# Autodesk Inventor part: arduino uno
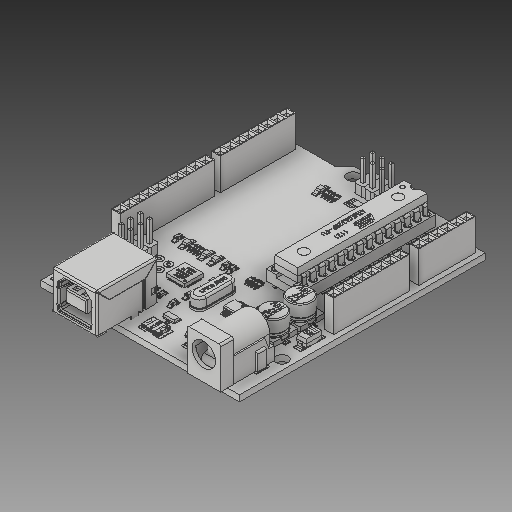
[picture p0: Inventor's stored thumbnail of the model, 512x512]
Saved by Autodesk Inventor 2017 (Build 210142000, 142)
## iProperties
Created: 2014-01
Part Number: arduino uno
Material: Générique
Description: STEP AP203
Document SubType Name: Modeling
Designer: ficho
Density: 1 g/cm^3
Appearance: Par défaut
Title: arduino uno.STEP
Author: A
Sending System: SolidWorks 2012
Preprocessor: SwSTEP 2.0
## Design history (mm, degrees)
feature "unoboard blue_1:1"
feature "47uf CAP Dcase_2:1"
feature "47uf CAP Dcase_2:2"
feature "USB SHELL_82:1"
feature "USB core_83:1"
feature "usb top contact_84:1"
feature "usb btm contact_85:1"
feature "usb btm contact_86:1"
feature "usb top contact_87:1"
feature "power jack_4:1"
feature "power jack_4:2"
feature "47uf CAP Dcase_5:1"
feature "47uf CAP Dcase_5:2"
feature "crystal_6:1"
feature "2pin_header__02_7:1"
feature "nano - reg_8:1"
feature "led_9:1"
feature "led_9:2"
feature "2pin_header__02_10:1"
feature "dip28_53:1"
feature "dip socket pin_54:1"
feature "dip socket pin_55:1"
feature "dip socket pin_56:1"
feature "dip socket pin_57:1"
feature "dip socket pin_58:1"
feature "dip socket pin_59:1"
feature "dip socket pin_60:1"
feature "dip socket pin_61:1"
feature "dip socket pin_62:1"
feature "dip socket pin_63:1"
feature "dip socket pin_64:1"
feature "dip socket pin_65:1"
feature "dip socket pin_66:1"
feature "dip socket pin_67:1"
feature "dip socket pin_68:1"
feature "dip socket pin_69:1"
feature "dip socket pin_70:1"
feature "dip socket pin_71:1"
feature "dip socket pin_72:1"
feature "dip socket pin_73:1"
feature "dip socket pin_74:1"
feature "dip socket pin_75:1"
feature "dip socket pin_76:1"
feature "dip socket pin_77:1"
feature "dip socket pin_78:1"
feature "dip socket pin_79:1"
feature "dip socket pin_80:1"
feature "dip socket pin_81:1"
feature "2pin_header__02_12:1"
feature "2pin_header__02_13:1"
feature "2pin_header__02_14:1"
feature "2pin_header__02_15:1"
feature "atmega16u2_16:1"
feature "led_17:1"
feature "led_17:2"
feature "led_18:1"
feature "led_18:2"
feature "led_19:1"
feature "led_19:2"
feature "8 PORT HEADER_20:1"
feature "8 PORT HEADER_21:1"
feature "6 PORT HEADER_22:1"
feature "10 PORT HEADER_23:1"
feature "ATMEL328P_24:1"
feature "ATMEL328P_24:2"
feature "ATMEL328P_24:3"
feature "ATMEL328P_24:4"
feature "ATMEL328P_24:5"
feature "ATMEL328P_24:6"
feature "ATMEL328P_24:7"
feature "ATMEL328P_24:8"
feature "ATMEL328P_24:9"
feature "ATMEL328P_24:10"
feature "ATMEL328P_24:11"
feature "102 RESISTOR PACK_25:1"
feature "102 RESISTOR PACK_25:2"
feature "102 RESISTOR PACK_25:3"
feature "102 RESISTOR PACK_25:4"
feature "102 RESISTOR PACK_25:5"
feature "102 RESISTOR PACK_25:6"
feature "102 RESISTOR PACK_25:7"
feature "102 RESISTOR PACK_25:8"
feature "102 RESISTOR PACK_25:9"
feature "102 RESISTOR PACK_25:10"
feature "102 RESISTOR PACK_26:1"
feature "102 RESISTOR PACK_26:2"
feature "102 RESISTOR PACK_26:3"
feature "102 RESISTOR PACK_26:4"
feature "102 RESISTOR PACK_26:5"
feature "102 RESISTOR PACK_26:6"
feature "102 RESISTOR PACK_26:7"
feature "102 RESISTOR PACK_26:8"
feature "102 RESISTOR PACK_26:9"
feature "102 RESISTOR PACK_26:10"
feature "103 RESISTOR PACK_27:1"
feature "103 RESISTOR PACK_27:2"
feature "103 RESISTOR PACK_27:3"
feature "103 RESISTOR PACK_27:4"
feature "103 RESISTOR PACK_27:5"
feature "103 RESISTOR PACK_27:6"
feature "103 RESISTOR PACK_27:7"
feature "103 RESISTOR PACK_27:8"
feature "103 RESISTOR PACK_27:9"
feature "103 RESISTOR PACK_27:10"
feature "220 RESISTOR PACK_28:1"
feature "220 RESISTOR PACK_28:2"
feature "220 RESISTOR PACK_28:3"
feature "220 RESISTOR PACK_28:4"
feature "220 RESISTOR PACK_28:5"
feature "220 RESISTOR PACK_28:6"
feature "220 RESISTOR PACK_28:7"
feature "220 RESISTOR PACK_28:8"
feature "220 RESISTOR PACK_28:9"
feature "220 RESISTOR PACK_28:10"
feature "16mhz crystal - measured_29:1"
feature "PADS001_30:1"
feature "PADS001_30:2"
feature "PADS001_30:3"
feature "PADS001_30:4"
feature "603 cap on pad_31:1"
feature "ssot3_32:1"
feature "mf-msmf050-2_33:1"
feature "603 cap on pad_34:1"
feature "603 cap on pad_35:1"
feature "lmv358_36:1"
feature "603 cap on pad_37:1"
feature "603 cap on pad_38:1"
feature "603 cap on pad_39:1"
feature "603 cap on pad_40:1"
feature "603 cap on pad_41:1"
feature "lp2985dgkr_42:1"
feature "cd1206 diode_43:1"
feature "cd1206 diode_43:2"
feature "cd1206 diode_43:3"
feature "cd1206 diode_43:4"
feature "cd1206 diode_43:5"
feature "cd1206 diode_44:1"
feature "cd1206 diode_44:2"
feature "cd1206 diode_44:3"
feature "cd1206 diode_44:4"
feature "cd1206 diode_44:5"
feature "603 resistor_45:1"
feature "603 resistor_45:2"
feature "603 resistor_45:3"
feature "603 resistor_45:4"
feature "blm21_46:1"
feature "m7 diode_47:1"
feature "MLC0603_48:1"
feature "MLC0603_48:2"
feature "MLC0603_48:3"
feature "MLC0603_48:4"
feature "MLC0603_49:1"
feature "MLC0603_49:2"
feature "MLC0603_49:3"
feature "MLC0603_49:4"
feature "RESET CORE_51:1"
feature "RESET CORE_51:2"
feature "RESET_52:1"
node "Solide1"
node "Solide2"
node "Solide3"
node "Solide4"
node "Solide5"
node "Solide6"
node "Solide7"
node "Solide8"
node "Solide9"
node "Solide10"
node "Solide11"
node "Solide12"
node "Solide13"
node "Solide14"
node "Solide15"
node "Solide16"
node "Solide17"
node "Solide18"
node "Solide19"
node "Solide20"
node "Solide21"
node "Solide22"
node "Solide23"
node "Solide24"
node "Solide25"
node "Solide26"
node "Solide27"
node "Solide28"
node "Solide29"
node "Solide30"
node "Solide31"
node "Solide32"
node "Solide33"
node "Solide34"
node "Solide35"
node "Solide36"
node "Solide37"
node "Solide38"
node "Solide39"
node "Solide40"
node "Solide41"
node "Solide42"
node "Solide43"
node "Solide44"
node "Solide45"
node "Solide46"
node "Solide47"
node "Solide48"
node "Solide49"
node "Solide50"
node "Solide51"
node "Solide52"
node "Solide53"
node "Solide54"
node "Solide55"
node "Solide56"
node "Solide57"
node "Solide58"
node "Solide59"
node "Solide60"
node "Solide61"
node "Solide62"
node "Solide63"
node "Solide64"
node "Solide65"
node "Solide66"
node "Solide67"
node "Solide68"
node "Solide69"
node "Solide70"
node "Solide71"
node "Solide72"
node "Solide73"
node "Solide74"
node "Solide75"
node "Solide76"
node "Solide77"
node "Solide78"
node "Solide79"
node "Solide80"
node "Solide81"
node "Solide82"
node "Solide83"
node "Solide84"
node "Solide85"
node "Solide86"
node "Solide87"
node "Solide88"
node "Solide89"
node "Solide90"
node "Solide91"
node "Solide92"
node "Solide93"
node "Solide94"
node "Solide95"
node "Solide96"
node "Solide97"
node "Solide98"
node "Solide99"
node "Solide100"
node "Solide101"
node "Solide102"
node "Solide103"
node "Solide104"
node "Solide105"
node "Solide106"
node "Solide107"
node "Solide108"
node "Solide109"
node "Solide110"
node "Solide111"
node "Solide112"
node "Solide113"
node "Solide114"
node "Solide115"
node "Solide116"
node "Solide117"
node "Solide118"
node "Solide119"
node "Solide120"
node "Solide121"
node "Solide122"
node "Solide123"
node "Solide124"
node "Solide125"
node "Solide126"
node "Solide127"
node "Solide128"
node "Solide129"
node "Solide130"
node "Solide131"
node "Solide132"
node "Solide133"
node "Solide134"
node "Solide135"
node "Solide136"
node "Solide137"
node "Solide138"
node "Solide139"
node "Solide140"
node "Solide141"
node "Solide142"
node "Solide143"
node "Solide144"
node "Solide145"
node "Solide146"
node "Solide147"
node "Solide148"
node "Solide149"
node "Solide150"
node "Solide151"
node "Solide152"
node "Solide153"
node "Solide154"
node "Solide155"
node "Solide156"
node "Solide157"
node "Solide158"
